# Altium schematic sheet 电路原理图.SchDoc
size 419 x 297 mm
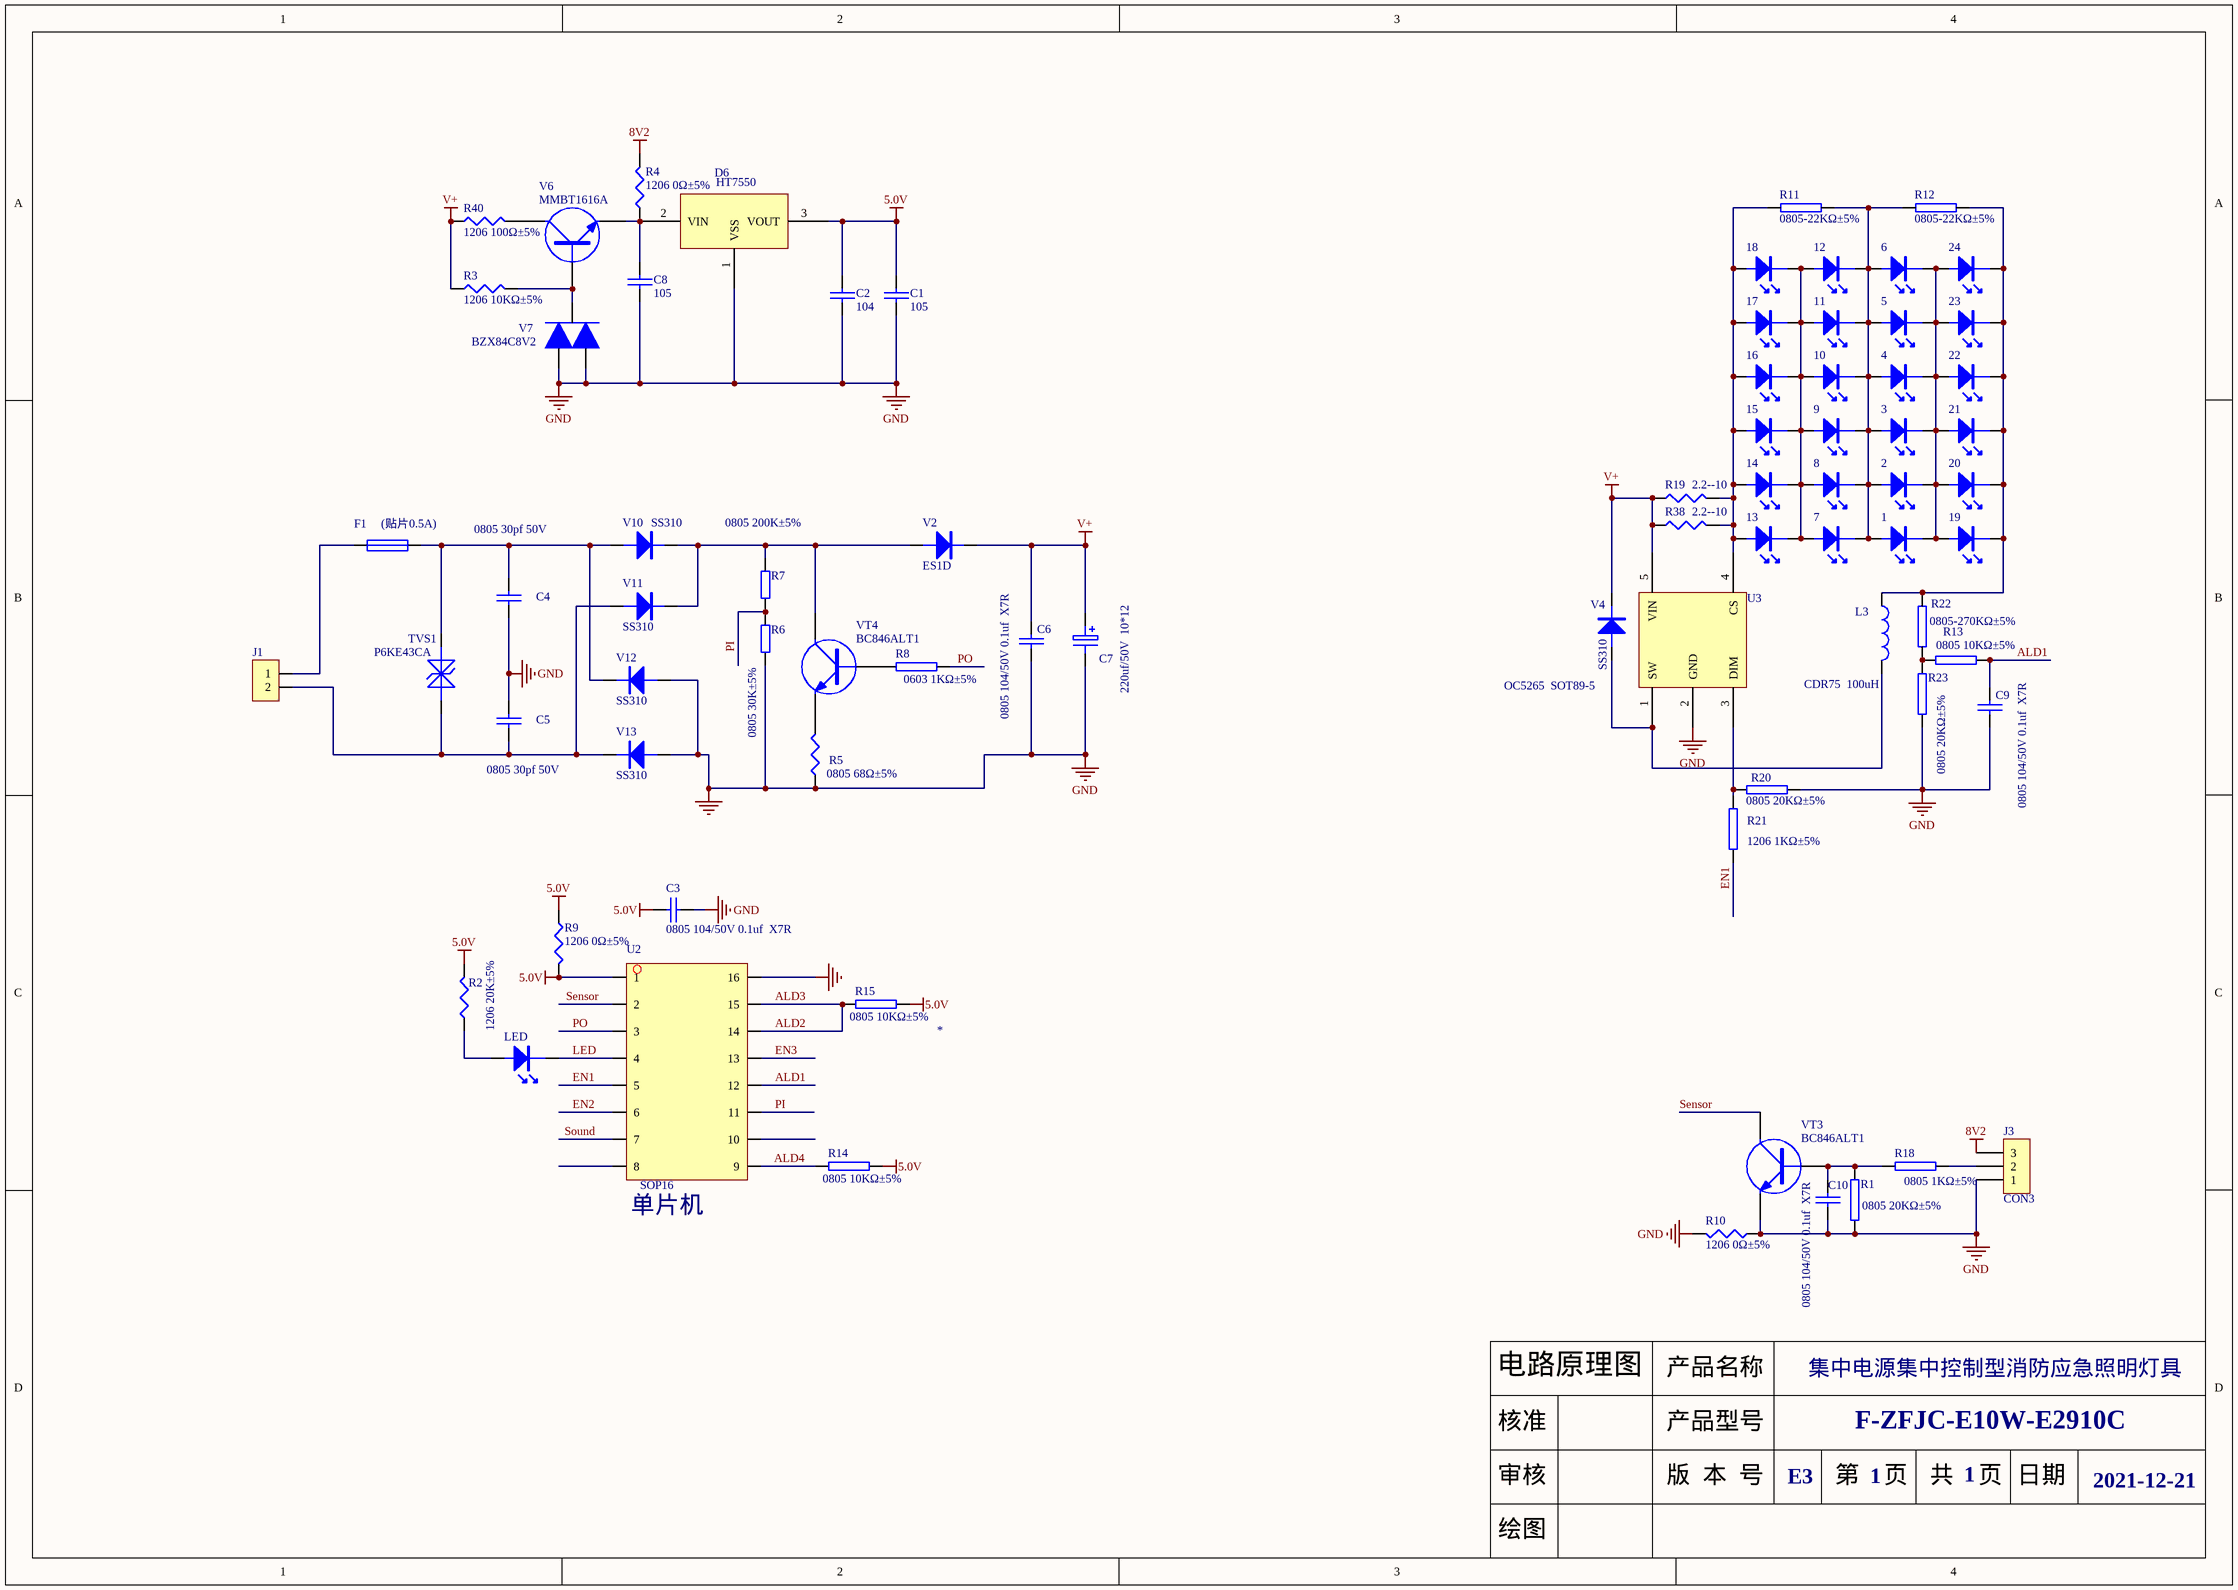
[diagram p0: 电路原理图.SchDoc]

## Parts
1  (no value)  [2835]
2  (no value)  [2835]
3  (no value)  [2835]
4  (no value)  [2835]
5  (no value)  [2835]
6  (no value)  [2835]
7  (no value)  [2835]
8  (no value)  [2835]
9  (no value)  [2835]
10  (no value)  [2835]
11  (no value)  [2835]
12  (no value)  [2835]
13  (no value)  [2835]
14  (no value)  [2835]
15  (no value)  [2835]
16  (no value)  [2835]
17  (no value)  [2835]
18  (no value)  [2835]
19  (no value)  [2835]
20  (no value)  [2835]
21  (no value)  [2835]
22  (no value)  [2835]
23  (no value)  [2835]
24  (no value)  [2835]
C1  105  [0805-C]
C2  104  [0805-c]
C3  0805 104/50V 0.1uf  X7R  [0805-c]
C4  0805 30pf 50V  [0805-c]
C5  0805 30pf 50V  [0805-c]
C6  0805 104/50V 0.1uf  X7R  [0805-c]
C7  220uf/50V  10*12  [CE10-m]
C8  105  [0805-C]
C9  0805 104/50V 0.1uf  X7R  [0805-c]
C10  0805 104/50V 0.1uf  X7R  [0805-c]
D6  HT7550  [SOT-89]
F1  (贴片0.5A)  [贴片保险]
J1  BUS  [SMT_J2]  (value not drawn)
J3  CON3  [PH2.0-3PWb]
L3  CDR75  100uH  [L8]
LED  (no value)  [led0805]
R1  0805 20KΩ±5%  [0805]
R2  1206 20K±5%  [1206]
R3  1206 10KΩ±5%  [1206]
R4  1206 0Ω±5%  [1206]
R5  0805 68Ω±5%  [0805]
R6  0805 30K±5%  [0805]
R7  0805 200K±5%  [0805]
R8  0603 1KΩ±5%  [0805]
R9  1206 0Ω±5%  [1206]
R10  1206 0Ω±5%  [1206]
R11  0805-22KΩ±5%  [0805]
R12  0805-22KΩ±5%  [0805]
R13  0805 10KΩ±5%  [0805]
R14  0805 10KΩ±5%  [0805]
R15  0805 10KΩ±5%  [0805]
R18  0805 1KΩ±5%  [0805]
R19  2.2--10  [1206]
R20  0805 20KΩ±5%  [0805]
R21  1206 1KΩ±5%  [1206]
R22  0805-270KΩ±5%  [0805]
R23  0805 20KΩ±5%  [0805]
R38  2.2--10  [1206]
R40  1206 100Ω±5%  [1206]
TVS1  P6KE43CA  [SMT_TVS]
U2  SOP16  [SOP-16b]
U3  OC5265  SOT89-5  [SOT-89-5]
V2  ES1D  [DO-214AC]
V4  SS310  [VDM7]
V6  MMBT1616A  [SOT-23]
V7  BZX84C8V2  [SOT-23]
V10  SS310  [VDM7]
V11  SS310  [VDM7]
V12  SS310  [VDM7]
V13  SS310  [VDM7]
VT3  BC846ALT1  [SOT-23]
VT4  BC846ALT1  [SOT-23]

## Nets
5.0V: C1.2 C2.2 C3.1 D6.3(VOUT) R2.2 R9.1 R9.2 R14.1 R15.1 U2.1
8V2: J3.3 R4.2
GND: C1.1 C2.1 C3.2 C4.2 C5.1 C6.2 C7.2 C8.1 C9.2 C10.2 D6.1(VSS) J3.1 R1.2 R5.1 R6.1 R10.1 R10.2 R20.1 R23.1 U2.16 U3.2(GND) V7.1 V7.2 V12.A V13.A VT3.2(E)
V+: C6.1 C7.1 R3.1 R19.1 R38.1 R40.1 U3.5(VIN) V2.K V4.K
ALD1: C9.1 R13.1 U2.12
ALD2: R15.2 U2.14 U2.15  [also labelled ALD3]
ALD4: R14.2 U2.9
EN1: R21.1 U2.5
EN2: U2.6
EN3: U2.13
LED: LED.K U2.4
PI: R6.2 R7.1 U2.11
PO: R8.2 U2.3
Sensor: U2.2 VT3.3(C)
Sound: U2.7
Net1_A: 1.A 2.A 3.A 4.A 5.A 6.A 7.K 8.K 9.K 10.K 11.K 12.K R11.1 R12.2
Net1_K: 1.K 2.K 3.K 4.K 5.K 6.K 19.A 20.A 21.A 22.A 23.A 24.A
Net7_A: 7.A 8.A 9.A 10.A 11.A 12.A 13.K 14.K 15.K 16.K 17.K 18.K
Net13_A: 13.A 14.A 15.A 16.A 17.A 18.A R11.2 R19.2 R38.2 U3.4(CS)
Net19_K: 19.K 20.K 21.K 22.K 23.K 24.K L3.1 R12.1 R22.2
NetC4_1: C4.1 F1.2 TVS1.A V10.A V12.K
NetC5_2: C5.2 J1.2 TVS1.K V11.A V13.K
NetC8_2: C8.2 D6.2(VIN) R4.1 V6.2(E)
NetC10_1: C10.1 R1.1 R18.1 VT3.1(B)
NetF1_1: F1.1 J1.1
NetJ3_2: J3.2 R18.2
NetL3_2: L3.2 U3.1(SW) V4.A
NetLED_A: LED.A R2.1
NetR3_2: R3.2 V6.1(B) V7.3
NetR5_2: R5.2 VT4.2(E)
NetR7_2: R7.2 V2.A V10.K V11.K VT4.3(C)
NetR8_1: R8.1 VT4.1(B)
NetR13_2: R13.2 R22.1 R23.2
NetR20_2: R20.2 R21.2 U3.3(DIM)
NetR40_2: R40.2 V6.3(C)

Not connected (* = marked no-connect by the designer): U2 8 10

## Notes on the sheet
- (near U2) 单片机
- 集中电源集中控制型消防应急照明灯具
- F-ZFJC-E10W-E2910C
- E3
- 1
- 2021-12-21

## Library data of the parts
1-24 = LED: 料号: 4.3.LED.235; 名称: 灯珠P2835SL1-03-34-65E-0; 型号规格: 色域65-0，电流150mA，电压DC3.2~DC3.4V，色温6500K，显指80，亮度65-70LM
C1 C2 C8 = CAP
C3 C6 C9 C10 = CAP: 料号: 4.1.CTX.004; 型号规格: 104/50V ±10% X7R 5000H RoHS; 名称: 0603封装贴片电容
C4 C5 = CAP: 料号: 4.1.CTX.054; 型号规格: 30PF/50V ±10% X7R 5000H RoHS; 名称: 0603封装贴片电容
C7 = ELECTRO1: 料号: 4.1.C.113; 型号规格: 330UF/50V 10*16 105℃ 误差±20% 5000-10000H 脚长(3.2-3.5mm); 名称: 电解电容
D6 = LDO
F1 = FUSE1: 料号: 4.3.X.111; 型号规格: 仓 24F系列 快断保险管 2A250V; 名称: 贴片保险管
J1 = CON2: 新料: 无
L3 = INDUCTOR: 料号: 4.5.LG.151; 型号规格: CD54-100uH; 名称: 贴片电感
LED = LED: 料号: 4.3.LED.250; 名称: 发光二极管; 型号规格: C0805UG-ES 高亮白发绿贴片 VF:2.8-3.0 IV:250-300 WLD:515-520  IF:30MA
R1 R20 = RES2: 料号: 4.2.RTX.003; 型号规格: 103(10KΩ) ±5%; 名称: 0603封装贴片电阻
R2 = RES1: 料号: 4.2.RTD.246; 型号规格: 15R(15Ω) ±1%RoHS; 名称: 0805封装贴片电阻
R3 R4 R9 R10 R40 = RES1
R5 = RES1: 料号: 4.2.RTD.244; 型号规格: 680(68Ω) ±5%; 名称: 0805封装贴片电阻
R6 = RES: 料号: 4.2.RTD.044; 型号规格: 203(20KΩ) ±5%; 名称: 0805封装贴片电阻
R7 = RES: 料号: 4.2.RTD.130; 型号规格: 274(270KΩ) ±5%; 名称: 0805封装贴片电阻
R8 R14 R15 R21 = RES2: 料号: 4.2.RTX.002; 型号规格: 102(1KΩ) ±5%; 名称: 0603封装贴片电阻
R11 R12 R22 = RES1: 料号: 4.2.RTX.009; 型号规格: 204(200KΩ) ±5%; 名称: 0603封装贴片电阻
R13 R23 = RES2: 料号: 4.2.RTX.035A; 型号规格: 203(20KΩ) ±1%; 名称: 0603封装贴片电阻
R18 = RES2: 料号: 无; 名称: 0603封装贴片电阻
R19 R38 = RES1: 料号: 调试待定; 名称: 1206贴片封装电阻
TVS1 = TVS1: 料号: 4.3.DT.064; 型号规格: 瞬态二极管 P6KE43CA  SMT_TVS; 名称: 贴片瞬态二极管
U3 = BP1360: 料号: 新料; 名称: 贴片IC
V2 = DIODE: 料号: 4.3.D.033; 型号规格: ES1D 1A/200V SMA -55~125℃ RoHS，编带; 名称: 贴片超快恢复二极管
V4 V10-V13 = DIODE: pin to pad: A>1 K>2; 料号: 4.3.DT.065; 型号规格: SS310 SMA 3A/100V  RoHS; 名称: 贴片肖特基二极
V6 VT3 VT4 = NPN
V7 = BZX84C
